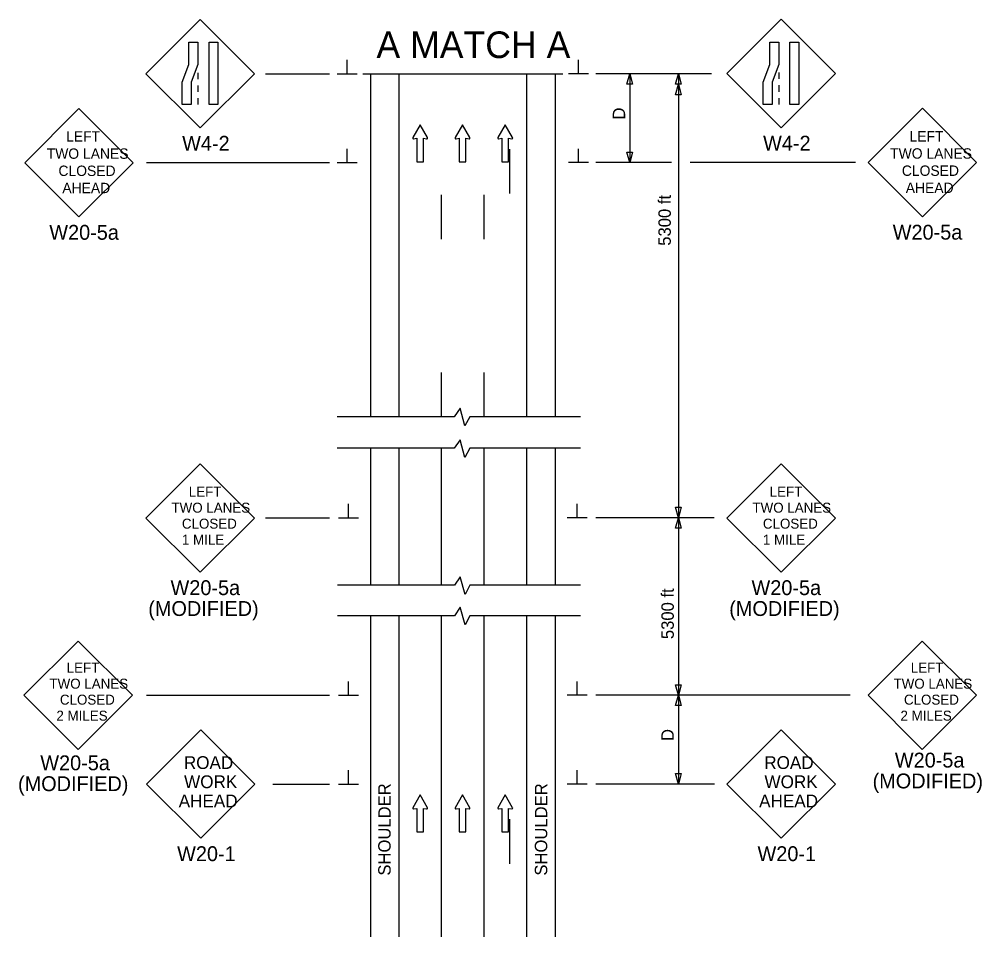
# Model space of a CAD drawing. Extents: x 16563 to 19504, y 6261 to 8279.
# Drawn here: x 17846 to 18388, y 7695 to 8212 of the extents above; entities that cross this region are included whole.
import ezdxf

# ---------------------------------------------------------------- set-up
doc = ezdxf.new("R2010")
doc.units = 0
for name, color, linetype in [('ALI_LEGAL_EX', 7, 'Continuous'), ('MT_SCRATCH_LEVEL_E', 7, 'Continuous'), ('PAVT_EDGE_EX', 7, 'Continuous'), ('TRAFFIC_SIGNS_PR', 7, 'Continuous'), ('TYPICAL_TEXT_DIMEN_PR', 7, 'Continuous')]:
    doc.layers.add(name, color=color, linetype=linetype)

msp = doc.modelspace()

# ---------------------------------------------------------------- linework, layer by layer
at = {"layer": 'ALI_LEGAL_EX'}
for p, q in [((18083.71, 7893.35), (18083.71, 7970.5)), ((18107.71, 7893.35), (18107.71, 7970.5)), ((18083.71, 7695.4), (18083.71, 7876.21)), ((18107.71, 7695.4), (18107.71, 7876.21))]:
    msp.add_line(p, q, dxfattribs=at)
for points in [[(18122.04, 8138.93), (18122.04, 8113.93)], [(18083.71, 8088.26), (18083.71, 8113.26)], [(18107.71, 8088.26), (18107.71, 8113.26)], [(18083.71, 7988.26), (18083.71, 8013.26)], [(18107.71, 7988.26), (18107.71, 8013.26)], [(18083.71, 7893.35), (18083.71, 7918.35)], [(18107.71, 7893.35), (18107.71, 7918.35)], [(18083.71, 7795.4), (18083.71, 7820.4)], [(18107.71, 7795.4), (18107.71, 7820.4)], [(18122.04, 7761.54), (18122.04, 7736.54)], [(18083.71, 7695.4), (18083.71, 7720.4)], [(18107.71, 7695.4), (18107.71, 7720.4)]]:
    msp.add_lwpolyline(points, dxfattribs=at)
at = {"layer": 'MT_SCRATCH_LEVEL_E'}
for p, q in [((18071.71, 8152.67), (18067.6, 8145.43)), ((18075.85, 8145.43), (18071.71, 8152.67)), ((18095.61, 8152.67), (18091.5, 8145.43)), ((18099.76, 8145.43), (18095.61, 8152.67)), ((18119.66, 8152.67), (18115.55, 8145.43)), ((18123.81, 8145.43), (18119.66, 8152.67)), ((18068.08, 8144.74), (18069.85, 8145.06)), ((18069.85, 8145.06), (18069.85, 8131.8)), ((18073.6, 8131.8), (18073.6, 8145.06)), ((18073.6, 8145.06), (18075.37, 8144.74)), ((18091.98, 8144.74), (18093.76, 8145.06)), ((18093.76, 8145.06), (18093.76, 8131.8)), ((18097.5, 8131.8), (18097.5, 8145.06)), ((18097.5, 8145.06), (18099.28, 8144.74)), ((18116.03, 8144.74), (18117.81, 8145.06)), ((18117.81, 8145.06), (18117.81, 8131.8)), ((18121.55, 8131.8), (18121.55, 8145.06)), ((18121.55, 8145.06), (18123.33, 8144.74)), ((18069.85, 8131.8), (18073.6, 8131.8)), ((18093.76, 8131.8), (18097.5, 8131.8)), ((18117.81, 8131.8), (18121.55, 8131.8)), ((18071.71, 7775.28), (18067.6, 7768.04)), ((18075.85, 7768.04), (18071.71, 7775.28)), ((18095.61, 7775.28), (18091.5, 7768.04)), ((18099.76, 7768.04), (18095.61, 7775.28)), ((18119.66, 7775.28), (18115.55, 7768.04)), ((18123.81, 7768.04), (18119.66, 7775.28)), ((18068.08, 7767.35), (18069.85, 7767.67)), ((18069.85, 7767.67), (18069.85, 7754.41)), ((18073.6, 7754.41), (18073.6, 7767.67)), ((18073.6, 7767.67), (18075.37, 7767.35)), ((18091.98, 7767.35), (18093.76, 7767.67)), ((18093.76, 7767.67), (18093.76, 7754.41)), ((18097.5, 7754.41), (18097.5, 7767.67)), ((18097.5, 7767.67), (18099.28, 7767.35)), ((18116.03, 7767.35), (18117.81, 7767.67)), ((18117.81, 7767.67), (18117.81, 7754.41)), ((18121.55, 7754.41), (18121.55, 7767.67)), ((18121.55, 7767.67), (18123.33, 7767.35)), ((18069.85, 7754.41), (18073.6, 7754.41)), ((18093.76, 7754.41), (18097.5, 7754.41)), ((18117.81, 7754.41), (18121.55, 7754.41))]:
    msp.add_line(p, q, dxfattribs=at)
for centre, start, end in [((18068, 8145.2), 150.4248, 279.9638), ((18075.44, 8145.2), 260.0362, 29.7731), ((18091.91, 8145.2), 150.4248, 279.9638), ((18099.35, 8145.2), 260.0362, 29.7731), ((18115.96, 8145.2), 150.4248, 279.9638), ((18123.4, 8145.2), 260.0362, 29.7731), ((18068, 7767.81), 150.4248, 279.9638), ((18075.44, 7767.81), 260.0362, 29.7731), ((18091.91, 7767.81), 150.4248, 279.9638), ((18099.35, 7767.81), 260.0362, 29.7731), ((18115.96, 7767.81), 150.4248, 279.9638), ((18123.4, 7767.81), 260.0362, 29.7731)]:
    msp.add_arc(centre, 0.463, start, end, dxfattribs=at)
at = {"layer": 'PAVT_EDGE_EX'}
for p, q in [((18043.71, 8181.41), (18043.71, 7988.26)), ((18059.71, 8181.41), (18059.71, 7988.26)), ((18131.71, 8181.41), (18131.71, 7988.26)), ((18147.71, 8181.41), (18147.71, 7988.26)), ((18043.71, 7970.5), (18043.71, 7893.36)), ((18059.71, 7970.5), (18059.71, 7893.36)), ((18131.71, 7970.52), (18131.71, 7893.36)), ((18147.71, 7970.52), (18147.71, 7893.36)), ((18043.71, 7876.22), (18043.71, 7695.4)), ((18059.71, 7876.22), (18059.71, 7695.4)), ((18131.71, 7876.22), (18131.71, 7695.4)), ((18147.71, 7876.22), (18147.71, 7695.4))]:
    msp.add_line(p, q, dxfattribs=at)
at = {"layer": 'TRAFFIC_SIGNS_PR'}
for p, q in [((17947.87, 8212.01), (17917.33, 8181.46)), ((17978.42, 8181.46), (17947.87, 8212.01)), ((18275.07, 8212.11), (18244.52, 8181.56)), ((18305.61, 8181.56), (18275.07, 8212.11)), ((17917.33, 8181.46), (17947.87, 8150.91)), ((17946.47, 8182.01), (17946.47, 8178.41)), ((17947.87, 8150.91), (17978.42, 8181.46)), ((18244.52, 8181.56), (18275.07, 8151.01)), ((18273.66, 8182.11), (18273.66, 8178.51)), ((18275.07, 8151.01), (18305.61, 8181.56)), ((17946.47, 8174.81), (17946.47, 8171.21)), ((18273.66, 8174.91), (18273.66, 8171.31)), ((17946.47, 8167.61), (17946.47, 8164.01)), ((18273.66, 8167.71), (18273.66, 8164.11)), ((17879.6, 8161.88), (17849.05, 8131.33)), ((17910.15, 8131.33), (17879.6, 8161.88)), ((18354.61, 8161.96), (18324.06, 8131.41)), ((18385.15, 8131.41), (18354.61, 8161.96)), ((17849.05, 8131.33), (17879.6, 8100.79)), ((17879.6, 8100.79), (17910.15, 8131.33)), ((18324.06, 8131.41), (18354.61, 8100.86)), ((18354.61, 8100.86), (18385.15, 8131.41)), ((17947.88, 7961.77), (17917.33, 7931.22)), ((17978.42, 7931.22), (17947.88, 7961.77)), ((18275.08, 7961.77), (18244.53, 7931.22)), ((18305.62, 7931.22), (18275.08, 7961.77)), ((17917.33, 7931.22), (17947.88, 7900.68)), ((17947.88, 7900.68), (17978.42, 7931.22)), ((18244.53, 7931.22), (18275.08, 7900.68)), ((18275.08, 7900.68), (18305.62, 7931.22)), ((17879.16, 7861.95), (17848.62, 7831.41)), ((17909.71, 7831.41), (17879.16, 7861.95)), ((18354.54, 7861.95), (18323.99, 7831.41)), ((18385.09, 7831.41), (18354.54, 7861.95)), ((17848.62, 7831.41), (17879.16, 7800.86)), ((17879.16, 7800.86), (17909.71, 7831.41)), ((18323.99, 7831.41), (18354.54, 7800.86)), ((18354.54, 7800.86), (18385.09, 7831.41)), ((17948.17, 7811.95), (17917.63, 7781.41)), ((17978.72, 7781.41), (17948.17, 7811.95)), ((18275.06, 7811.95), (18244.51, 7781.41)), ((18305.6, 7781.41), (18275.06, 7811.95)), ((17917.63, 7781.41), (17948.17, 7750.86)), ((17948.17, 7750.86), (17978.72, 7781.41)), ((18244.51, 7781.41), (18275.06, 7750.86)), ((18275.06, 7750.86), (18305.6, 7781.41))]:
    msp.add_line(p, q, dxfattribs=at)
for points in [[(17946.47, 8199.16), (17946.47, 8186.59), (17942.71, 8176.59), (17942.71, 8164.01), (17937.65, 8164.01), (17937.65, 8176.59), (17941.42, 8186.59), (17941.42, 8199.16)], [(17957.87, 8199.16), (17957.87, 8164.01), (17952.82, 8164.01), (17952.82, 8199.16)], [(18273.66, 8199.26), (18273.66, 8186.68), (18269.9, 8176.69), (18269.9, 8164.11), (18264.85, 8164.11), (18264.85, 8176.69), (18268.61, 8186.68), (18268.61, 8199.26)], [(18285.07, 8199.26), (18285.07, 8164.11), (18280.01, 8164.11), (18280.01, 8199.26)]]:
    msp.add_lwpolyline(points, close=True, dxfattribs=at)
at = {"layer": 'TYPICAL_TEXT_DIMEN_PR'}
for p, q in [((18030.58, 8181.41), (18030.58, 8189.19)), ((18030.58, 8181.41), (18030.58, 8189.19)), ((18160.83, 8181.41), (18160.83, 8189.19)), ((17984.71, 8181.41), (18020.71, 8181.41)), ((17994.71, 8181.41), (18020.71, 8181.41)), ((18024.96, 8181.41), (18036.21, 8181.41)), ((18024.96, 8181.41), (18036.21, 8181.41)), ((18039.38, 8181.41), (18152.03, 8181.41)), ((18166.46, 8181.41), (18155.21, 8181.41)), ((18208.83, 8181.41), (18170.71, 8181.41)), ((18188.2, 8175.55), (18189.77, 8181.41)), ((18189.77, 8181.41), (18189.77, 8131.41)), ((18189.77, 8181.41), (18191.34, 8175.55)), ((18235.8, 8181.41), (18208.83, 8181.41)), ((18215.57, 8175.55), (18217.15, 8181.41)), ((18217.15, 8181.41), (18217.15, 7931.41)), ((18217.15, 8181.41), (18218.72, 8175.55)), ((18189.77, 8175.55), (18188.2, 8175.55)), ((18191.34, 8175.55), (18189.77, 8175.55)), ((18217.15, 8175.55), (18215.57, 8175.55)), ((18215.57, 8169.63), (18217.15, 8175.49)), ((18218.72, 8175.55), (18217.15, 8175.55)), ((18217.15, 8175.49), (18218.72, 8169.63)), ((18217.15, 8169.63), (18215.57, 8169.63)), ((18218.72, 8169.63), (18217.15, 8169.63)), ((18030.58, 8131.41), (18030.58, 8139.19)), ((18160.83, 8131.41), (18160.83, 8139.19)), ((18189.77, 8131.41), (18188.2, 8137.27)), ((18188.2, 8137.27), (18189.77, 8137.27)), ((18189.77, 8137.27), (18191.34, 8137.27)), ((18191.34, 8137.27), (18189.77, 8131.41)), ((17917.6, 8131.41), (18020.71, 8131.41)), ((18024.96, 8131.41), (18036.21, 8131.41)), ((18166.46, 8131.41), (18155.21, 8131.41)), ((18213.3, 8131.41), (18170.71, 8131.41)), ((18316.83, 8131.41), (18223.73, 8131.41)), ((18094.22, 7993.06), (18090.97, 7988.26)), ((18096.96, 7983.12), (18094.22, 7993.06)), ((18090.97, 7988.26), (18025.03, 7988.26)), ((18099.71, 7988.26), (18096.96, 7983.12)), ((18162.04, 7988.26), (18099.71, 7988.26)), ((18094.22, 7975.3), (18090.97, 7970.5)), ((18096.96, 7965.36), (18094.22, 7975.3)), ((18090.97, 7970.5), (18025.03, 7970.5)), ((18099.71, 7970.5), (18096.96, 7965.36)), ((18162.04, 7970.5), (18099.71, 7970.5)), ((18031.33, 7931.41), (18031.33, 7939.19)), ((18160.08, 7931.41), (18160.08, 7939.19)), ((18217.15, 7931.41), (18215.57, 7937.27)), ((18215.57, 7937.27), (18217.15, 7937.27)), ((18217.15, 7937.27), (18218.72, 7937.27)), ((18218.72, 7937.27), (18217.15, 7931.41)), ((17984.71, 7931.41), (18020.71, 7931.41)), ((18025.71, 7931.41), (18036.96, 7931.41)), ((18165.71, 7931.41), (18154.46, 7931.41)), ((18237.33, 7931.41), (18170.71, 7931.41)), ((18215.57, 7925.55), (18217.15, 7931.41)), ((18217.15, 7931.41), (18217.15, 7831.41)), ((18217.15, 7931.41), (18218.72, 7925.55)), ((18217.15, 7925.55), (18215.57, 7925.55)), ((18218.72, 7925.55), (18217.15, 7925.55)), ((18094.31, 7898.15), (18091.06, 7893.35)), ((18097.05, 7888.21), (18094.31, 7898.15)), ((18091.06, 7893.35), (18025.12, 7893.35)), ((18099.8, 7893.35), (18097.05, 7888.21)), ((18162.13, 7893.35), (18099.8, 7893.35)), ((18094.31, 7881.01), (18091.06, 7876.21)), ((18097.05, 7871.07), (18094.31, 7881.01)), ((18091.06, 7876.21), (18025.12, 7876.21)), ((18099.8, 7876.21), (18097.05, 7871.07)), ((18162.13, 7876.21), (18099.8, 7876.21)), ((18031.33, 7831.41), (18031.33, 7839.19)), ((18160.08, 7831.41), (18160.08, 7839.19)), ((18217.15, 7831.41), (18215.57, 7837.27)), ((18215.57, 7837.27), (18217.15, 7837.27)), ((18217.15, 7837.27), (18218.72, 7837.27)), ((18218.72, 7837.27), (18217.15, 7831.41)), ((17917.55, 7831.41), (18020.71, 7831.41)), ((18025.71, 7831.41), (18036.96, 7831.41)), ((18165.71, 7831.41), (18154.46, 7831.41)), ((18313.86, 7831.41), (18170.71, 7831.41)), ((18215.57, 7825.55), (18217.15, 7831.41)), ((18217.15, 7831.41), (18217.15, 7781.41)), ((18217.15, 7831.41), (18218.72, 7825.55)), ((18217.15, 7825.55), (18215.57, 7825.55)), ((18218.72, 7825.55), (18217.15, 7825.55)), ((18031.33, 7781.41), (18031.33, 7789.19)), ((18160.08, 7781.41), (18160.08, 7789.19)), ((18217.15, 7781.41), (18215.57, 7787.27)), ((18215.57, 7787.27), (18217.15, 7787.27)), ((18217.15, 7787.27), (18218.72, 7787.27)), ((18218.72, 7787.27), (18217.15, 7781.41)), ((17988.77, 7781.41), (18020.71, 7781.41)), ((18025.71, 7781.41), (18036.96, 7781.41)), ((18165.71, 7781.41), (18154.46, 7781.41)), ((18237.57, 7781.41), (18170.71, 7781.41))]:
    msp.add_line(p, q, dxfattribs=at)

# ---------------------------------------------------------------- texts
at = {"layer": 'TRAFFIC_SIGNS_PR'}
for s, height, p in [('LEFT', 5.85, (17872.33, 8143.19)), ('LEFT', 5.85, (18347.34, 8143.26)), ('W4-2', 8.37, (17937.7, 8138.05)), ('W4-2', 8.37, (18264.89, 8138.14)), ('TWO LANES', 5.85, (17861.44, 8133.51)), ('TWO LANES', 5.85, (18336.45, 8133.59)), ('CLOSED', 5.85, (17868.03, 8123.84)), ('CLOSED', 5.85, (18343.03, 8123.91)), ('AHEAD', 5.85, (17870.22, 8114.16)), ('AHEAD', 5.85, (18345.22, 8114.24)), ('W20-5a', 8.37, (17862.88, 8087.92)), ('W20-5a', 8.37, (18337.89, 8087.99)), ('LEFT', 5.625, (17941.41, 7943.23)), ('LEFT', 5.625, (18268.61, 7943.23)), ('TWO LANES', 5.625, (17931.69, 7934.23)), ('TWO LANES', 5.625, (18258.89, 7934.23)), ('CLOSED', 5.625, (17937.56, 7925.23)), ('CLOSED', 5.625, (18264.77, 7925.23)), ('1 MILE', 5.625, (17937.56, 7916.23)), ('1 MILE', 5.625, (18264.76, 7916.23)), ('W20-5a', 8.37, (17931.16, 7887.81)), ('W20-5a', 8.37, (18258.36, 7887.81)), ('(MODIFIED)', 8.37, (17918.62, 7876.06)), ('(MODIFIED)', 8.37, (18245.82, 7876.06)), ('LEFT', 5.625, (17872.69, 7844.11)), ('LEFT', 5.625, (18348.07, 7844.11)), ('TWO LANES', 5.625, (17862.97, 7835.11)), ('TWO LANES', 5.625, (18338.35, 7835.11)), ('CLOSED', 5.625, (17868.85, 7826.11)), ('CLOSED', 5.625, (18344.23, 7826.11)), ('2 MILES', 5.625, (17866.88, 7817.11)), ('2 MILES', 5.625, (18342.26, 7817.11)), ('W20-5a', 8.37, (17857.8, 7789.15)), ('ROAD', 7.2, (17938.66, 7789.89)), ('ROAD', 7.2, (18265.54, 7789.89)), ('W20-5a', 8.37, (18339.09, 7790.69)), ('(MODIFIED)', 8.37, (17845.26, 7777.41)), ('WORK', 7.2, (17938.78, 7779.09)), ('WORK', 7.2, (18265.66, 7779.09)), ('(MODIFIED)', 8.37, (18326.55, 7778.95)), ('AHEAD', 7.2, (17935.75, 7768.28)), ('AHEAD', 7.2, (18262.64, 7768.28)), ('W20-1', 8.37, (17934.87, 7737.99)), ('W20-1', 8.37, (18261.75, 7737.99))]:
    msp.add_text(s, height=height, dxfattribs=at).set_placement(p)
at = {"layer": 'TYPICAL_TEXT_DIMEN_PR'}
msp.add_text('A MATCH A', height=15, dxfattribs=at).set_placement((18047.12, 8190.24))
for s, p in [('D', (18187.21, 8155.63)), ('5300 ft', (18212.91, 8084.54)), ('5300 ft', (18214.59, 7863.01)), ('D', (18214.59, 7805.63)), ('SHOULDER', (18055.13, 7729.82)), ('SHOULDER', (18143.33, 7729.82))]:
    msp.add_text(s, height=7, rotation=90, dxfattribs=at).set_placement(p)

doc.saveas('drawing.dxf')
